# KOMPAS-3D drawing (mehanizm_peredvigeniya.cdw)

Referenced files: механизм передвижения.cdw
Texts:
  СДМ1-12.00.000 СБ
  Механизм передвижения грузавой тележки сборочный чертеж
  Zver
  Microsoft
  Текст на чертеже
  Размерные надписи
  Шероховатость
  Линия-выноска #1
  Линия-выноска #2
  Линия-выноска #3
  Отклонения формы и база
  Заголовок таблицы
  Ячейка таблицы
  Стрелка вида
  Обозначение изменения
  Фигурная скобка
  Номер узла
  Марка координационной оси
  VRCB
  Выносная надпись
  Обозначение узла
  Марка/позиционное обозначение с линией-выноской
  Марка/позиционное обозначение на линии
  Марка/позиционное обозначение без линии-выноски
  Техническая характеристика
  Электродвигатель:
  Редуктор:
  мощность, кВт                                                   9,6
  1.   Размеры для справок
  2.  Неуказанные предельные отклонения: H14, h14 IT14 2
  3. Редуктор заполнить маслом М-8А (ГОСТ 10541-78).
  4. Тормоз  заполнить маслом АМГ (ГОСТ 6704-53).
  Технические требования
  POLYLINE_STYLE_0.18_RGB_0_0_0
  ACAD_ISO10W100_RGB_0_0_0_SC_1_THICK_0.15
  ACAD_ISO10W100_RGB_0_0_0_SC_0.5_THICK_0.15
  ACAD_ISO04W100_RGB_0_0_0_SC_1_THICK_0.3
  Механизм передвижения
  грузавой тележки
  сборочный чертеж
  Кузьмич Д.Н.
  Передня Л.И.
  СДМ1-12.00.000 СБ-
Dimensions and other numbers on the sheet: 7; 1178; 230; 223; 315; 1184; 2165; 882; 120; 400; 45; 48; 1; 2; 3; 4; 5; 8; 12; 14; 6; 9; 13; 15; 10; 11; 16; 17; 90; 1:5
